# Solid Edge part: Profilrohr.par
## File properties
Dokumentum tartalom típus: 0
Last saved by: bmolnar
Revision: 78
Sűrűség: 0,000 kg/m^3
Pontosság: 0,990
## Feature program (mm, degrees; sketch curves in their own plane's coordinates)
base feature "unnamed BaseFeature 1"
thread "unnamed Thread 1"
thread "Menet_2"  ThreadDepth = 7.5 mm
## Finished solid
Body 1: solid body, 165 faces, 370 edges, 262 vertices, 3 separate solids.
  Faces by surface: plane 100, cylinder 43, cone 18, torus 4
  Edges by curve: line 256, circle 106, curve on surface 8
Bounding box of the edges (mm; curved faces can reach further): 80.000 x 86.000 x 52.000, from (-40, -40, 0) to (40, 46, 52).
Cylindrical faces by radius (mm): R1.6 x2, R4 x2, R4.283 x4, R4.55 x7, R4.555 x1, R6.9 x2, R7 x14, R31.5 x1, R32.35 x2, R32.55 x2, R34.1 x2, R53 x4
Conical faces (half-angle, radius in mm at the cone's reference point): 30 deg R31.825 x2, 30 deg R32.6387 x2, 45 deg R4.25 x4, 45 deg R4.533 x2, 45 deg R6.65 x4, 45 deg R32.7 x2, 45 deg R32.8 x2
Toroidal faces (ring radius, tube radius in mm): R33.9 r0.2 x4
Planar faces by outward normal: +x 9, +y 11, +z 12, -x 9, -y 9, -z 10, oblique 40
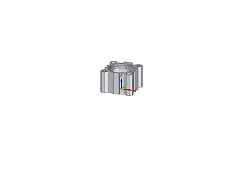
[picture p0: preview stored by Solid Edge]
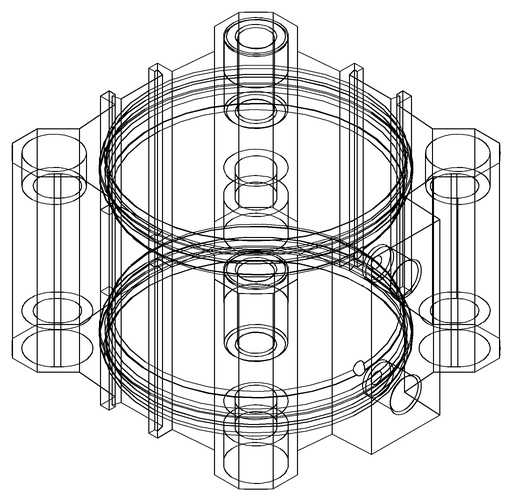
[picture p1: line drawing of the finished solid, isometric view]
